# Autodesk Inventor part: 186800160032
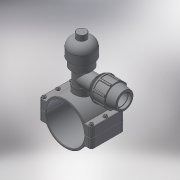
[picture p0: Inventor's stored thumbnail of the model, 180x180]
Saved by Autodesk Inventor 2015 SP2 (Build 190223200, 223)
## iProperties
Created: 2017-05
Part Number: 186800160032
Material: Generic
Description: PLASSON MECHANICAL TAPPING VALVE 160-32
Document SubType Name: Modeling
Designer: KIM
Density: 1 g/cm^3
Appearance: Default
Author: KIM
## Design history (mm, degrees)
derived "18680.ipt"
feature "Solid1::18680.ipt"
feature "Solid2::18680.ipt"
tag "TaggingFeature1"
body "Solid1"
other parameters: "d0" = 176, "d1" = 223, "d4" = 145, "d5" = 0, "d6" = 11.15, "d7" = 223, "d8" = 0.1, "d10" = 0, "d11" = 1.6, "d14" = 50.6376, "d20" = 1.6, "d23" = 1.6, "d36" = 15, "d37" = 12, "d38" = 88, "d39" = 0, "d40" = 3, "d41" = 5, "d42" = 0, "d44" = 3, "d45" = 0, "d46" = 1.6, "d51" = 117, "d52" = 38.952, "d53" = 25, "d54" = 0, "d55" = 32, "d57" = 0, "d58" = 172.8, "d60" = 0, "d62" = 15, "d63" = 12, "d66" = 121, "d67" = 32, "d68" = 11.25, "d69" = 27, "d70" = 64, "d71" = 48, "d72" = 1.92857, "d73" = 51.2, "d74" = 120 deg, "d75" = 48, "d76" = 10 deg, "d77" = 57.6, "d78" = 40.5, "d79" = 67, "d80" = 25.6, "d81" = 135, "d82" = 6.7, "d87" = 19.28571, "d90" = 59.52, "d91" = 35 deg, "d92" = 17.5 deg, "d94" = 0, "d96" = 360 deg, "d98" = 0.64, "d99" = 73.7, "d100" = 38.4, "d101" = 135 deg, "d102" = 1.28, "d105" = 3.2, "d106" = 0, "d107" = 0.1, "d109" = 50.6376, "d112" = 34.85714, "d113" = 4.5, "d116" = 0, "d121" = 46.7424, "d122" = 77.904, "d123" = 66.2184, "d124" = 45 deg, "d125" = 219.6, "d126" = 244, "d127" = 146.4, "d128" = 1, "B_" = 32, "G_" = 38.952, "A_" = 117, "L_" = 223, "L_1" = 145, "l_2" = 25, "d_1" = 32, "E_" = 64, "l_" = 67, "H_" = 135, "H_2" = 244
